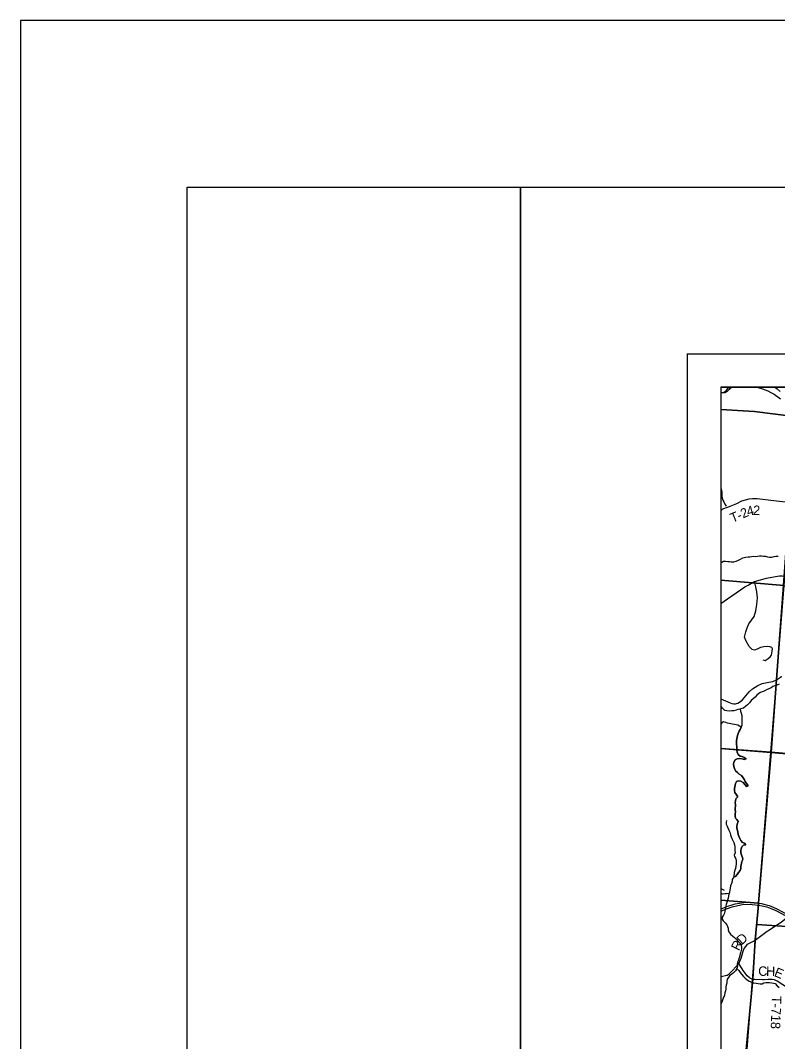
# Model space of a CAD drawing. Extents: x 0 to 42, y 0 to 22.
# Drawn here: x 0 to 2.271, y 18.938 to 22 of the extents above; entities that cross this region are included whole.
import ezdxf

# ---------------------------------------------------------------- set-up
doc = ezdxf.new("R2010")
doc.units = 0
for name, color, linetype in [('GM_X_City_Street', 7, 'Continuous'), ('GM_X_County_Road', 7, 'Continuous'), ('GM_X_County_Road_Text', 7, 'Continuous'), ('GM_X_Minor_Lake', 7, 'Continuous'), ('GM_X_Minor_River', 7, 'Continuous'), ('GM_X_Section', 7, 'Continuous'), ('GM_X_State_Route', 7, 'Continuous'), ('GM_X_Township_Road', 7, 'Continuous'), ('GM_X_Township_Road_Text', 7, 'Continuous'), ('GM_X_Unincorporated', 7, 'Continuous'), ('GM_X_US_Shield', 7, 'Continuous'), ('SH_Border', 7, 'Continuous'), ('SH_Cut_Line', 7, 'Continuous'), ('SH_Data', 7, 'Continuous')]:
    doc.layers.add(name, color=color, linetype=linetype)

msp = doc.modelspace()

# ---------------------------------------------------------------- linework, layer by layer
at = {"layer": 'GM_X_City_Street'}
msp.add_lwpolyline([(2.1, 20.5303), (2.1017, 20.5307), (2.1064, 20.5352)], dxfattribs=at)
at = {"layer": 'GM_X_County_Road'}
for points in [[(2.2092, 20.9), (2.2254, 20.8951), (2.2412, 20.8896), (2.2507, 20.8846), (2.2608, 20.8787), (2.2791, 20.8653)], [(2.1, 20.2514), (2.1001, 20.2515), (2.1205, 20.265), (2.1724, 20.301), (2.1823, 20.3064), (2.1978, 20.3151), (2.2018, 20.3171), (2.2056, 20.3187), (2.2227, 20.3234), (2.2371, 20.3271), (2.2641, 20.3322), (2.2761, 20.3339), (2.2848, 20.3341), (2.2904, 20.3335), (2.3014, 20.3317)], [(2.2434, 19.2711), (2.2569, 19.2799), (2.2816, 19.2958), (2.2921, 19.3047), (2.3002, 19.312), (2.3013, 19.3128), (2.3041, 19.3148), (2.3056, 19.3159), (2.3123, 19.3209), (2.3174, 19.3246), (2.3328, 19.3281), (2.34, 19.3312), (2.3453, 19.336), (2.3486, 19.3398)], [(2.1982, 19.2391), (2.2034, 19.242), (2.2119, 19.2479), (2.2392, 19.2683), (2.2434, 19.2711)], [(2.1, 19.1328), (2.119, 19.1365), (2.1251, 19.1405), (2.136, 19.1519), (2.1541, 19.1712), (2.1579, 19.1782), (2.161, 19.188), (2.1672, 19.2087), (2.1708, 19.2164), (2.176, 19.224), (2.1807, 19.2295), (2.1982, 19.2391)]]:
    msp.add_lwpolyline(points, dxfattribs=at)
at = {"layer": 'GM_X_Minor_Lake'}
for points in [[(2.1, 20.8844), (2.1027, 20.8846), (2.1098, 20.8854), (2.1161, 20.8892), (2.1214, 20.896), (2.1244, 20.9)], [(2.1615, 19.8801), (2.1519, 19.8863), (2.1466, 19.8873), (2.1414, 19.888), (2.135, 19.8896), (2.1301, 19.8903), (2.1252, 19.8915), (2.1203, 19.8928), (2.115, 19.8941), (2.1082, 19.8962), (2.1031, 19.8938), (2.1, 19.8892)], [(2.1448, 19.4321), (2.1492, 19.4381), (2.1531, 19.4444), (2.158, 19.4508), (2.16, 19.4563), (2.1608, 19.4625), (2.1615, 19.4675), (2.1629, 19.4724), (2.1639, 19.4775), (2.166, 19.4837), (2.1651, 19.49), (2.1634, 19.4947), (2.1616, 19.4995), (2.1609, 19.5048), (2.1609, 19.5111), (2.1611, 19.5158), (2.1634, 19.5219), (2.1682, 19.5264), (2.1752, 19.5273), (2.1718, 19.5326), (2.1654, 19.5349), (2.1609, 19.541), (2.157, 19.5469), (2.154, 19.5532), (2.1527, 19.5589), (2.1514, 19.5654), (2.1505, 19.5709), (2.1489, 19.5775), (2.1482, 19.584), (2.1493, 19.5897), (2.152, 19.5974), (2.1485, 19.6031), (2.1443, 19.6079), (2.1434, 19.614), (2.1439, 19.6197), (2.1443, 19.6274), (2.1439, 19.6322), (2.144, 19.6481), (2.1439, 19.6536), (2.1441, 19.66), (2.1453, 19.6653), (2.1512, 19.6712), (2.1477, 19.678), (2.1426, 19.6841), (2.1417, 19.6904), (2.1419, 19.697), (2.1423, 19.7018), (2.1433, 19.7069), (2.1447, 19.7118), (2.1474, 19.7179), (2.1538, 19.7195), (2.1602, 19.7183), (2.167, 19.7147), (2.1725, 19.7086), (2.1773, 19.7025), (2.1823, 19.7051), (2.1778, 19.711), (2.1738, 19.7177), (2.1718, 19.7224), (2.1677, 19.7287), (2.162, 19.735), (2.1555, 19.7398), (2.1506, 19.7442), (2.1449, 19.7497), (2.1418, 19.7562), (2.1395, 19.7628), (2.1388, 19.7691), (2.1391, 19.7757), (2.1436, 19.7822), (2.1497, 19.7853), (2.1565, 19.7861), (2.1641, 19.7854), (2.1707, 19.7835), (2.1764, 19.7852), (2.1706, 19.7898), (2.164, 19.7925), (2.1583, 19.7938), (2.1526, 19.7988), (2.1498, 19.8051), (2.1488, 19.8119), (2.1484, 19.817), (2.1481, 19.8229), (2.1474, 19.8299), (2.1472, 19.8347), (2.1476, 19.8409), (2.1484, 19.8458), (2.1492, 19.8508), (2.15, 19.8555), (2.1521, 19.8617), (2.1552, 19.868), (2.1583, 19.8738), (2.1615, 19.8801)], [(2.1171, 19.601), (2.1167, 19.5944), (2.1168, 19.5896), (2.1191, 19.584), (2.1212, 19.5788), (2.124, 19.5718), (2.1272, 19.5652), (2.1299, 19.558), (2.1316, 19.5515), (2.1331, 19.5468), (2.1365, 19.5401), (2.1399, 19.5348), (2.1414, 19.528), (2.1425, 19.5225), (2.1429, 19.517), (2.1428, 19.5106), (2.143, 19.5032), (2.1402, 19.4969), (2.1415, 19.4922), (2.1445, 19.4874), (2.146, 19.4812), (2.1466, 19.4755), (2.1466, 19.4704), (2.1458, 19.4635), (2.1441, 19.4563), (2.1426, 19.4514), (2.1405, 19.4446), (2.139, 19.4316)], [(2.139, 19.4316), (2.1448, 19.4321)]]:
    msp.add_lwpolyline(points, dxfattribs=at)
at = {"layer": 'GM_X_Minor_River'}
for points in [[(2.1, 20.5999), (2.1006, 20.5968), (2.102, 20.5905), (2.1031, 20.5848), (2.1037, 20.5795), (2.1038, 20.5748), (2.1042, 20.5674), (2.106, 20.5609), (2.109, 20.5558), (2.1125, 20.5493), (2.1169, 20.5434)], [(2.2725, 20.3922), (2.2659, 20.3923), (2.259, 20.391), (2.252, 20.3895), (2.2469, 20.3888), (2.2412, 20.39), (2.235, 20.3921), (2.2288, 20.3927), (2.2223, 20.3931), (2.2163, 20.3936), (2.2104, 20.3923), (2.2042, 20.3917), (2.1989, 20.392), (2.1926, 20.3914), (2.1877, 20.3907), (2.1822, 20.3898), (2.1752, 20.3893), (2.1703, 20.3884), (2.165, 20.3871), (2.1583, 20.3833), (2.1528, 20.3807), (2.1454, 20.3768), (2.1386, 20.3755), (2.1316, 20.3754), (2.1267, 20.3758), (2.1216, 20.3762), (2.1148, 20.3774), (2.1081, 20.3768), (2.103, 20.3746), (2.1, 20.3733)], [(2.2757, 20.0094), (2.268, 20.0068), (2.2617, 20.0044), (2.2566, 20.0025), (2.2511, 19.9989), (2.2442, 19.9954), (2.2372, 19.992), (2.2304, 19.9888), (2.2247, 19.9862), (2.2199, 19.984), (2.2148, 19.9814), (2.2082, 19.9765)], [(2.2082, 19.9765), (2.2032, 19.9706), (2.1971, 19.965), (2.1916, 19.9605), (2.1861, 19.9537), (2.1807, 19.9475), (2.1756, 19.9431), (2.1689, 19.9379), (2.1634, 19.9366), (2.1575, 19.9343), (2.1513, 19.933), (2.146, 19.9312), (2.1395, 19.9299), (2.1333, 19.929), (2.1255, 19.9289), (2.118, 19.9291), (2.1121, 19.9307), (2.1057, 19.937), (2.1023, 19.9417), (2.1, 19.9434)], [(2.1582, 19.9346), (2.159, 19.9286), (2.1612, 19.922), (2.1631, 19.9159), (2.1632, 19.9096), (2.1632, 19.9026), (2.1637, 19.8977), (2.1637, 19.8916), (2.1633, 19.8869), (2.1615, 19.8801), (2.1583, 19.8738), (2.1552, 19.868), (2.1521, 19.8617), (2.15, 19.8555), (2.1492, 19.8508), (2.1484, 19.8458), (2.1476, 19.8409), (2.1472, 19.8347), (2.1474, 19.8299), (2.1481, 19.8229), (2.1484, 19.817), (2.1488, 19.8119), (2.1498, 19.8051), (2.1526, 19.7988), (2.1583, 19.7938), (2.164, 19.7925), (2.1706, 19.7898), (2.1764, 19.7852), (2.1707, 19.7835), (2.1641, 19.7854), (2.1565, 19.7861), (2.1497, 19.7853), (2.1436, 19.7822), (2.1391, 19.7757), (2.1388, 19.7691), (2.1395, 19.7628), (2.1418, 19.7562), (2.1449, 19.7497), (2.1506, 19.7442), (2.1555, 19.7398), (2.162, 19.735), (2.1677, 19.7287), (2.1718, 19.7224), (2.1738, 19.7177), (2.1778, 19.711), (2.1823, 19.7051), (2.1773, 19.7025), (2.1725, 19.7086), (2.167, 19.7147), (2.1602, 19.7183), (2.1538, 19.7195), (2.1474, 19.7179), (2.1447, 19.7118), (2.1433, 19.7069), (2.1423, 19.7018), (2.1419, 19.697), (2.1417, 19.6904), (2.1426, 19.6841), (2.1477, 19.678), (2.1512, 19.6712), (2.1453, 19.6653), (2.1441, 19.66), (2.1439, 19.6536), (2.144, 19.6481), (2.1439, 19.6322), (2.1443, 19.6274), (2.1439, 19.6197), (2.1434, 19.614), (2.1443, 19.6079), (2.1485, 19.6031), (2.152, 19.5974), (2.1493, 19.5897), (2.1482, 19.584), (2.1489, 19.5775), (2.1505, 19.5709), (2.1514, 19.5654), (2.1527, 19.5589), (2.154, 19.5532), (2.157, 19.5469), (2.1609, 19.541), (2.1654, 19.5349), (2.1718, 19.5326), (2.1752, 19.5273), (2.1682, 19.5264), (2.1634, 19.5219), (2.1611, 19.5158), (2.1609, 19.5111), (2.1609, 19.5048), (2.1616, 19.4995), (2.1634, 19.4947), (2.1651, 19.49), (2.166, 19.4837), (2.1639, 19.4775), (2.1629, 19.4724), (2.1615, 19.4675), (2.1608, 19.4625), (2.16, 19.4563), (2.158, 19.4508), (2.1531, 19.4444), (2.1492, 19.4381), (2.1448, 19.4321)], [(2.1448, 19.4321), (2.139, 19.4316), (2.1346, 19.4238), (2.134, 19.4181), (2.132, 19.4115), (2.1299, 19.4049), (2.1285, 19.3977), (2.1276, 19.3926), (2.126, 19.385), (2.1246, 19.3797), (2.1235, 19.3742), (2.1221, 19.368), (2.1207, 19.3613), (2.1186, 19.3545), (2.1165, 19.3487), (2.1149, 19.3407), (2.1133, 19.3331), (2.1129, 19.3282), (2.1118, 19.3231), (2.1087, 19.317), (2.1049, 19.3102), (2.1044, 19.3046), (2.1076, 19.2996), (2.1131, 19.2939), (2.1181, 19.2876), (2.1209, 19.2823), (2.122, 19.2775), (2.1222, 19.2728), (2.1248, 19.2663), (2.1299, 19.26), (2.1366, 19.2541), (2.1415, 19.2497), (2.1464, 19.2447), (2.1522, 19.2381), (2.1582, 19.2316), (2.161, 19.2264), (2.1623, 19.22), (2.1627, 19.2143), (2.1603, 19.2063), (2.1586, 19.2005), (2.1574, 19.1956), (2.1553, 19.1886), (2.153, 19.1821), (2.1503, 19.1755), (2.1493, 19.1691), (2.1502, 19.1643), (2.1498, 19.1592), (2.1479, 19.1543), (2.1441, 19.1494), (2.1382, 19.1435), (2.1334, 19.14), (2.1269, 19.1349), (2.1233, 19.1292), (2.1197, 19.1243), (2.1187, 19.1181), (2.1183, 19.1122), (2.1169, 19.1069), (2.1159, 19.102), (2.1151, 19.0946), (2.1143, 19.0898), (2.1126, 19.0836), (2.1112, 19.0756), (2.1085, 19.0703), (2.1066, 19.0652), (2.1047, 19.0586), (2.1012, 19.052), (2.1, 19.0488)], [(2.125, 19.3812), (2.1174, 19.3807), (2.1125, 19.3802), (2.1065, 19.38), (2.1, 19.3812), (2.1, 19.3812)], [(2.1489, 19.157), (2.1547, 19.151), (2.1584, 19.1445), (2.1623, 19.1392), (2.1685, 19.1331), (2.1738, 19.1277), (2.1789, 19.1234), (2.1855, 19.1191), (2.193, 19.1155), (2.1989, 19.1139), (2.2064, 19.1122), (2.2187, 19.1102), (2.2244, 19.1103), (2.2295, 19.1132), (2.2361, 19.1146), (2.2414, 19.1148), (2.2464, 19.1142), (2.253, 19.1134), (2.2581, 19.1124), (2.2634, 19.1114), (2.2699, 19.1049), (2.2752, 19.0998)]]:
    msp.add_lwpolyline(points, dxfattribs=at)
at = {"layer": 'GM_X_Section'}
for points in [[(2.2901, 20.3056), (2.8507, 20.2571), (2.8154, 19.7575), (2.7915, 19.7594), (2.2508, 19.8053)], [(2.7915, 19.7594), (2.7467, 19.2527), (2.2083, 19.2886), (2.2132, 19.3524), (2.2508, 19.8053)], [(2.2083, 19.2886), (2.7467, 19.2527), (2.7049, 18.7525), (2.6719, 18.7548), (2.5842, 18.763), (2.1704, 18.7909), (2.1744, 18.851)]]:
    msp.add_lwpolyline(points, close=True, dxfattribs=at)
at = {"layer": 'GM_X_State_Route'}
for points in [[(3.2907, 20.9), (2.2624, 20.9), (2.2694, 20.8953), (2.2785, 20.8868)], [(2.1, 19.9657), (2.1282, 19.9534), (2.1338, 19.9514), (2.1394, 19.9506), (2.1443, 19.9505), (2.1478, 19.9515), (2.1512, 19.9525), (2.1568, 19.9552), (2.1656, 19.9624), (2.1859, 19.9862), (2.1955, 19.9957), (2.2116, 20.0059), (2.2244, 20.0112), (2.2444, 20.0153), (2.256, 20.0171), (2.2675, 20.0228), (2.282, 20.0323), (2.2828, 20.0329)], [(2.1, 19.3343), (2.1176, 19.3422), (2.1312, 19.3469), (2.1437, 19.3506), (2.1564, 19.3529), (2.1696, 19.3546), (2.1838, 19.3553), (2.1985, 19.3548), (2.2103, 19.3535), (2.214, 19.3529), (2.2222, 19.3515), (2.2336, 19.3485), (2.2451, 19.3452), (2.257, 19.3407), (2.2685, 19.3357), (2.2983, 19.3198), (2.3056, 19.3159)], [(2.1, 19.3278), (2.1074, 19.3314), (2.1207, 19.337), (2.1349, 19.3416), (2.151, 19.3459), (2.1656, 19.3482), (2.1799, 19.3492), (2.1948, 19.349), (2.2135, 19.347), (2.2249, 19.3449), (2.2381, 19.3414), (2.253, 19.3361), (2.2657, 19.3303), (2.2825, 19.3217), (2.3002, 19.312)]]:
    msp.add_lwpolyline(points, dxfattribs=at)
at = {"layer": 'GM_X_Township_Road'}
msp.add_line((2.1, 19.3965), (2.1109, 19.392), dxfattribs=at)
for points in [[(2.1306, 20.9), (2.1258, 20.8934), (2.1196, 20.8867), (2.1161, 20.8847), (2.1129, 20.8835), (2.1066, 20.8827), (2.1, 20.8822)], [(2.1064, 20.5352), (2.1238, 20.5413), (2.148, 20.5513), (2.1634, 20.5588), (2.1745, 20.5627), (2.1854, 20.5655), (2.1955, 20.5667), (2.2099, 20.5665), (2.2672, 20.5593), (2.3032, 20.5556)], [(2.2269, 20.0819), (2.2337, 20.0808), (2.2427, 20.0862), (2.2485, 20.0912), (2.2524, 20.0962), (2.2546, 20.1084), (2.2556, 20.1149), (2.2531, 20.1192), (2.2474, 20.1214), (2.2402, 20.1224), (2.2294, 20.1217), (2.2194, 20.1189), (2.209, 20.1142), (2.2014, 20.1113), (2.1946, 20.1135), (2.1856, 20.1221), (2.1767, 20.1386), (2.1713, 20.1508), (2.172, 20.1544), (2.1756, 20.1662), (2.1792, 20.1781), (2.1846, 20.1899), (2.1921, 20.2011), (2.2, 20.2126), (2.205, 20.2294), (2.2086, 20.2488), (2.21, 20.2686), (2.2083, 20.2862), (2.205, 20.3016), (2.2018, 20.3171)], [(2.2903, 20.3337), (2.2674, 20.023), (2.2513, 19.8044), (2.4976, 19.7838)], [(2.4976, 19.7838), (2.2513, 19.8044), (2.2139, 19.3532), (2.2137, 19.3505), (2.2133, 19.3473), (2.2033, 19.2423), (2.1961, 19.1242), (2.1704, 18.8498), (2.1703, 18.8289), (2.1676, 18.7906), (2.1429, 18.4796), (2.1, 17.9374), (2.1, 16.7767), (2.1647, 16.7711), (2.5782, 16.7296)], [(2.2303, 19.1231), (2.2258, 19.1229), (2.2024, 19.1232), (2.1962, 19.124), (2.1868, 19.1287), (2.1792, 19.1342), (2.1678, 19.1502), (2.1541, 19.1712)], [(2.7396, 19.0736), (2.7042, 19.0651), (2.6971, 19.0624), (2.6906, 19.0588), (2.6867, 19.0561), (2.6426, 19.0064), (2.4016, 19.0244), (2.3304, 19.0725), (2.3034, 19.0962), (2.2691, 19.1188), (2.2618, 19.1224), (2.2542, 19.1239), (2.2422, 19.1239), (2.2303, 19.1231)]]:
    msp.add_lwpolyline(points, dxfattribs=at)
for points in [[(2.3349, 20.9), (2.1, 20.9), (2.1, 19.8165), (2.2513, 19.8044), (2.2674, 20.023), (2.2903, 20.3337), (2.3066, 20.5555), (2.3253, 20.8091), (2.3276, 20.8303)], [(2.1, 19.8165), (2.1, 17.9374), (2.1429, 18.4796), (2.1676, 18.7906), (2.1703, 18.8289), (2.1704, 18.8498), (2.1961, 19.1242), (2.2033, 19.2423), (2.2133, 19.3473), (2.2137, 19.3505), (2.2139, 19.3532), (2.2513, 19.8044)]]:
    msp.add_lwpolyline(points, close=True, dxfattribs=at)
at = {"layer": 'GM_X_Unincorporated'}
for points in [[(2.3369, 20.9), (2.1, 20.9), (2.1, 20.8334), (2.2012, 20.8269), (2.3275, 20.8113)], [(2.1, 20.8334), (2.1, 20.3216), (2.2901, 20.3056), (2.3275, 20.8113), (2.2012, 20.8269)], [(2.1, 20.3216), (2.1, 19.8161), (2.2508, 19.8053), (2.2901, 20.3056)], [(2.1, 19.8161), (2.1, 19.362), (2.2132, 19.3524), (2.2508, 19.8053)], [(2.1, 19.362), (2.1, 18.8579), (2.1744, 18.851), (2.2083, 19.2886), (2.2132, 19.3524)]]:
    msp.add_lwpolyline(points, close=True, dxfattribs=at)
at = {"layer": 'GM_X_US_Shield'}
msp.add_line((2.1383, 20.9), (2.1181, 20.9), dxfattribs=at)
msp.add_arc((2.1282, 20.9358), 0.0372, 254.2801, 285.7199, dxfattribs=at)
at = {"layer": 'SH_Border'}
for points in [[(0.5, 21.5), (1.5, 21.5), (1.5, 0.5), (0.5, 0.5)], [(1.5, 21.5), (33.5, 21.5), (33.5, 0.5), (1.5, 0.5)]]:
    msp.add_lwpolyline(points, close=True, dxfattribs=at)
at = {"layer": 'SH_Cut_Line'}
msp.add_lwpolyline([(0, 0), (34, 0), (34, 22), (0, 22)], close=True, dxfattribs=at)
msp.add_lwpolyline([(8.604, 20.9), (2.1, 20.9), (2.1, 14.1)], dxfattribs=at)
at = {"layer": 'SH_Data'}
for p, q in [((2, 21), (9, 21)), ((2, 21), (2, 14)), ((2.1, 20.9), (2.1, 14.1)), ((2.1, 20.9), (8.9, 20.9))]:
    msp.add_line(p, q, dxfattribs=at)

# ---------------------------------------------------------------- texts
at = {"layer": 'GM_X_County_Road_Text'}
for s, rotation, p in [('R', 62.5814, (2.1547, 19.2076)), ('D', 42.6295, (2.1638, 19.2263))]:
    msp.add_text(s, height=0.0284, rotation=rotation, dxfattribs=at).set_placement(p)
at = {"layer": 'GM_X_Township_Road_Text'}
for s, height, rotation, p in [('T', 0.0284, 21.5181, (2.135, 20.493)), ('2', 0.0284, 25.0117, (2.1672, 20.506)), ('4', 0.0284, 15.0725, (2.1819, 20.513)), ('2', 0.0284, 356.6467, (2.1964, 20.5173)), ('-', 0.0284, 22.7667, (2.1554, 20.501)), ('C', 0.0284, 1.1398, (2.2129, 19.1343)), ('H', 0.0284, 358.4662, (2.2359, 19.1347)), ('E', 0.0284, 337.5516, (2.2582, 19.1346)), ('T-718', 0.02841, 267.7544, (2.2539, 19.075))]:
    msp.add_text(s, height=height, rotation=rotation, dxfattribs=at).set_placement(p)

doc.saveas('drawing.dxf')
